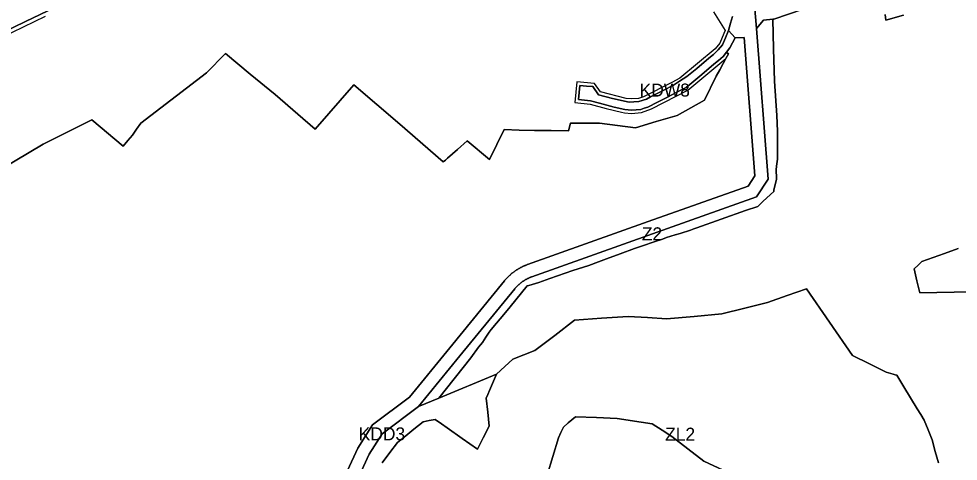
# Model space of a CAD drawing. Extents: x 7439486 to 7443435, y 5551288 to 5554556.
# Drawn here: x 7441363 to 7442085, y 5552904 to 5553244 of the extents above; entities that cross this region are included whole.
import ezdxf

# ---------------------------------------------------------------- set-up
doc = ezdxf.new("R2010")
doc.units = 0
for name, color, linetype in [('linie_rozgraniczajace', 7, 'Continuous'), ('linie_zabudowy_nieprzekraczalne', 7, 'Continuous'), ('oznaczenia_przeznaczen', 7, 'Continuous')]:
    doc.layers.add(name, color=color, linetype=linetype)

msp = doc.modelspace()

# ---------------------------------------------------------------- linework, layer by layer
at = {"layer": 'linie_rozgraniczajace'}
for points in [[(7441331.46, 5553224.04), (7441368.14, 5553241.69), (7441425.2, 5553269.15)], [(7441425.2, 5553269.15), (7441368.14, 5553241.69), (7441331.46, 5553224.04)], [(7441928.74, 5553254.3), (7441930.13, 5553236.35), (7441939.08, 5553120.56), (7441930.19, 5553106.89), (7441850.22, 5553078.58), (7441757.46, 5553045.52), (7441757.43, 5553045.51), (7441757.11, 5553045.39), (7441756.78, 5553045.27), (7441756.46, 5553045.14), (7441756.14, 5553045.01), (7441755.82, 5553044.88), (7441755.5, 5553044.74), (7441755.18, 5553044.6), (7441754.87, 5553044.46), (7441754.56, 5553044.31), (7441754.24, 5553044.16), (7441753.94, 5553044), (7441753.63, 5553043.84), (7441753.32, 5553043.68), (7441753.02, 5553043.52), (7441752.72, 5553043.35), (7441752.42, 5553043.18), (7441752.12, 5553043), (7441751.82, 5553042.82), (7441751.53, 5553042.64), (7441751.23, 5553042.45), (7441750.94, 5553042.26), (7441750.66, 5553042.07), (7441750.37, 5553041.87), (7441750.09, 5553041.67), (7441749.81, 5553041.47), (7441749.53, 5553041.26), (7441749.25, 5553041.05), (7441748.98, 5553040.84), (7441748.71, 5553040.62), (7441748.44, 5553040.4), (7441748.18, 5553040.18), (7441747.91, 5553039.96), (7441747.65, 5553039.73), (7441747.39, 5553039.5), (7441747.14, 5553039.27), (7441746.88, 5553039.03), (7441746.63, 5553038.79), (7441746.39, 5553038.55), (7441746.14, 5553038.3), (7441745.9, 5553038.05), (7441745.66, 5553037.8), (7441745.43, 5553037.55), (7441745.19, 5553037.29), (7441744.96, 5553037.03), (7441744.74, 5553036.77), (7441744.51, 5553036.5), (7441744.29, 5553036.24), (7441702.23, 5552984.74), (7441670.41, 5552945.79), (7441642.42, 5552924.8), (7441632.49, 5552909.09), (7441605.42, 5552850.4)], [(7441736.61, 5552976.52), (7441730.3, 5552970.8), (7441685.94, 5552952.27), (7441710.51, 5552983.35), (7441716.56, 5552991.33), (7441719.61, 5552995.1), (7441722.2, 5552999.2), (7441724.68, 5553002.99), (7441726.14, 5553005.01), (7441737.14, 5553018.12), (7441740.71, 5553022.47), (7441745.2, 5553027.89), (7441753.87, 5553038.56), (7441755.21, 5553038.95), (7441762.78, 5553041.2), (7441771.4, 5553044.24), (7441788.98, 5553050.44), (7441801.31, 5553054.34), (7441808.81, 5553057.13), (7441814.98, 5553059.43), (7441825.4, 5553063.3), (7441836.41, 5553067.18), (7441842.47, 5553069.38), (7441851.6, 5553072.43), (7441857.79, 5553074.51), (7441860.97, 5553075.71), (7441867.54, 5553077.9), (7441871.61, 5553078.77), (7441879.34, 5553081.49), (7441881.93, 5553082.33), (7441884.29, 5553083.17), (7441921.76, 5553096.4), (7441931.26, 5553099.7), (7441935.22, 5553103.66), (7441943.46, 5553111.13), (7441943.49, 5553112.19), (7441945.62, 5553120.7), (7441945.59, 5553121.33), (7441945.2, 5553127.75), (7441945.6, 5553130.5), (7441946.38, 5553135.9), (7441946.44, 5553145.5), (7441946.21, 5553157.51), (7441945.9, 5553169.52), (7441943.93, 5553196.03), (7441943.28, 5553220.79), (7441942.74, 5553243.51), (7441943.58, 5553243.59), (7441965.97, 5553251.17)], [(7441965.97, 5553251.17), (7441943.58, 5553243.59), (7441942.74, 5553243.51), (7441935.65, 5553242.87), (7441930.13, 5553236.35), (7441928.74, 5553254.3)], [(7441670.41, 5552945.79), (7441702.23, 5552984.74), (7441744.29, 5553036.24), (7441744.51, 5553036.5), (7441744.74, 5553036.77), (7441744.96, 5553037.03), (7441745.19, 5553037.29), (7441745.43, 5553037.55), (7441745.66, 5553037.8), (7441745.9, 5553038.05), (7441746.14, 5553038.3), (7441746.39, 5553038.55), (7441746.63, 5553038.79), (7441746.88, 5553039.03), (7441747.14, 5553039.27), (7441747.39, 5553039.5), (7441747.65, 5553039.73), (7441747.91, 5553039.96), (7441748.18, 5553040.18), (7441748.44, 5553040.4), (7441748.71, 5553040.62), (7441748.98, 5553040.84), (7441749.25, 5553041.05), (7441749.53, 5553041.26), (7441749.81, 5553041.47), (7441750.09, 5553041.67), (7441750.37, 5553041.87), (7441750.66, 5553042.07), (7441750.94, 5553042.26), (7441751.23, 5553042.45), (7441751.53, 5553042.64), (7441751.82, 5553042.82), (7441752.12, 5553043), (7441752.42, 5553043.18), (7441752.72, 5553043.35), (7441753.02, 5553043.52), (7441753.32, 5553043.68), (7441753.63, 5553043.84), (7441753.94, 5553044), (7441754.24, 5553044.16), (7441754.56, 5553044.31), (7441754.87, 5553044.46), (7441755.18, 5553044.6), (7441755.5, 5553044.74), (7441755.82, 5553044.88), (7441756.14, 5553045.01), (7441756.46, 5553045.14), (7441756.78, 5553045.27), (7441757.11, 5553045.39), (7441757.43, 5553045.51), (7441757.46, 5553045.52), (7441850.22, 5553078.58), (7441930.19, 5553106.89), (7441939.08, 5553120.56), (7441930.13, 5553236.35), (7441935.65, 5553242.87), (7441942.74, 5553243.51), (7441943.28, 5553220.79), (7441943.93, 5553196.03), (7441945.9, 5553169.52), (7441946.21, 5553157.51), (7441946.44, 5553145.5), (7441946.38, 5553135.9), (7441945.6, 5553130.5), (7441945.2, 5553127.75), (7441945.59, 5553121.33), (7441945.62, 5553120.7), (7441943.49, 5553112.19), (7441943.46, 5553111.13), (7441935.22, 5553103.66), (7441931.26, 5553099.7), (7441921.76, 5553096.4), (7441884.29, 5553083.17), (7441881.93, 5553082.33), (7441879.34, 5553081.49), (7441871.61, 5553078.77), (7441867.54, 5553077.9), (7441860.97, 5553075.71), (7441857.79, 5553074.51), (7441851.6, 5553072.43), (7441842.47, 5553069.38), (7441836.41, 5553067.18), (7441825.4, 5553063.3), (7441814.98, 5553059.43), (7441808.81, 5553057.13), (7441801.31, 5553054.34), (7441788.98, 5553050.44), (7441771.4, 5553044.24), (7441762.78, 5553041.2), (7441755.21, 5553038.95), (7441753.87, 5553038.56), (7441745.2, 5553027.89), (7441740.71, 5553022.47), (7441737.14, 5553018.12), (7441726.14, 5553005.01), (7441724.68, 5553002.99), (7441722.2, 5552999.2), (7441719.61, 5552995.1), (7441716.56, 5552991.33), (7441710.51, 5552983.35)], [(7441751.73, 5553054.01), (7441752.1, 5553054.16), (7441752.47, 5553054.32), (7441752.84, 5553054.47), (7441753.22, 5553054.61), (7441753.59, 5553054.75), (7441753.97, 5553054.89), (7441754.1, 5553054.94), (7441846.88, 5553088), (7441923.66, 5553115.19), (7441928.85, 5553123.17), (7441920.64, 5553229.41), (7441913.66, 5553229.13), (7441908.7, 5553234.81), (7441910.26, 5553240.49), (7441911.64, 5553245.76)], [(7441911.64, 5553245.76), (7441910.26, 5553240.49), (7441908.7, 5553234.81), (7441906.4, 5553229.31), (7441904.09, 5553223.82), (7441900.59, 5553220.11), (7441897.23, 5553216.54), (7441893.59, 5553213.51), (7441884.32, 5553205.78), (7441876.69, 5553199.42), (7441871.03, 5553195.83), (7441866.36, 5553192.86), (7441865.83, 5553192.6), (7441858.95, 5553189.09), (7441848.62, 5553183.81), (7441845.56, 5553181.97), (7441839.6, 5553180.32), (7441835.94, 5553180.11)], [(7442029.06, 5553247.24), (7442029.7, 5553242.69), (7442043.26, 5553246.77)], [(7442043.26, 5553246.77), (7442029.7, 5553242.69), (7442029.06, 5553247.24)], [(7441339.88, 5553122.65), (7441381.86, 5553147.53), (7441419.1, 5553166.1), (7441443.31, 5553145.86), (7441446.85, 5553150.19), (7441450.39, 5553154.53), (7441453.67, 5553159.13), (7441456.95, 5553163.74), (7441507.23, 5553202.43), (7441521.96, 5553217.26), (7441541.02, 5553201.41), (7441560.07, 5553185.57), (7441577.56, 5553170.56), (7441590.88, 5553159.13), (7441620.69, 5553193.1), (7441655.88, 5553162.75), (7441689.41, 5553133.83), (7441691.08, 5553135.29), (7441692.75, 5553136.75), (7441700.3, 5553143.38), (7441707.86, 5553150.01), (7441724.94, 5553135.66), (7441730.53, 5553147.23), (7441736.12, 5553158.8), (7441747.65, 5553158.23), (7441759.5, 5553158.1), (7441771.36, 5553157.96), (7441772.41, 5553157.95), (7441785.74, 5553157.8), (7441787.25, 5553163.56), (7441798.41, 5553163.56), (7441809.58, 5553163.56), (7441823.32, 5553161.83), (7441837.06, 5553160.09), (7441853.07, 5553164.84), (7441869.09, 5553169.59), (7441879.64, 5553175.51), (7441890.2, 5553181.43), (7441899.24, 5553199.74), (7441901.89, 5553204.63), (7441904.53, 5553209.53), (7441906.57, 5553213.29), (7441908.61, 5553217.05), (7441907.69, 5553217.83), (7441907.16, 5553218.28), (7441909.6, 5553221.55), (7441911.63, 5553225.34), (7441913.66, 5553229.13), (7441920.64, 5553229.41), (7441928.85, 5553123.17), (7441923.66, 5553115.19), (7441846.88, 5553088), (7441754.1, 5553054.94), (7441753.97, 5553054.89), (7441753.59, 5553054.75), (7441753.22, 5553054.61), (7441752.84, 5553054.47), (7441752.47, 5553054.32), (7441752.1, 5553054.16), (7441751.73, 5553054.01), (7441751.37, 5553053.85), (7441751, 5553053.69), (7441750.64, 5553053.52), (7441750.28, 5553053.35), (7441749.92, 5553053.17), (7441749.56, 5553053), (7441749.2, 5553052.81), (7441748.85, 5553052.63), (7441748.49, 5553052.44), (7441748.14, 5553052.25), (7441747.79, 5553052.05), (7441747.45, 5553051.85), (7441747.1, 5553051.65), (7441746.76, 5553051.44), (7441746.42, 5553051.24), (7441746.08, 5553051.02), (7441745.74, 5553050.81), (7441745.41, 5553050.59), (7441745.08, 5553050.36), (7441744.75, 5553050.14)], [(7441835.94, 5553180.11), (7441832.27, 5553179.89), (7441819.53, 5553182.48), (7441808.59, 5553185.45), (7441804.33, 5553191.74), (7441799.36, 5553192.21), (7441794.38, 5553192.68), (7441793.35, 5553181.73), (7441797.99, 5553181.29), (7441802.63, 5553180.85), (7441809.6, 5553178.96), (7441815.17, 5553177.45), (7441820.75, 5553175.93), (7441829.05, 5553174.16), (7441834.13, 5553173.66), (7441837.71, 5553173.92), (7441841.29, 5553174.19), (7441843.93, 5553175.11), (7441846.57, 5553176.03), (7441854.12, 5553179.89), (7441861.68, 5553183.74), (7441868.86, 5553187.4), (7441876.03, 5553191.06), (7441878.89, 5553193.45), (7441888.16, 5553201.17), (7441897.43, 5553208.9), (7441901.04, 5553211.91), (7441904.65, 5553214.91), (7441907.16, 5553218.28), (7441907.69, 5553217.83), (7441908.61, 5553217.05), (7441906.57, 5553213.29), (7441904.53, 5553209.53), (7441901.89, 5553204.63), (7441899.24, 5553199.74), (7441890.2, 5553181.43), (7441879.64, 5553175.51), (7441869.09, 5553169.59), (7441853.07, 5553164.84), (7441837.06, 5553160.09), (7441823.32, 5553161.83), (7441809.58, 5553163.56), (7441798.41, 5553163.56), (7441787.25, 5553163.56), (7441785.74, 5553157.8), (7441772.41, 5553157.95), (7441771.36, 5553157.96), (7441759.5, 5553158.1), (7441747.65, 5553158.23), (7441736.12, 5553158.8), (7441730.53, 5553147.23), (7441724.94, 5553135.66), (7441707.86, 5553150.01), (7441700.3, 5553143.38), (7441692.75, 5553136.75), (7441691.08, 5553135.29), (7441689.41, 5553133.83), (7441655.88, 5553162.75), (7441620.69, 5553193.1), (7441590.88, 5553159.13), (7441577.56, 5553170.56), (7441560.07, 5553185.57), (7441541.02, 5553201.41), (7441521.96, 5553217.26), (7441507.23, 5553202.43), (7441456.95, 5553163.74), (7441453.67, 5553159.13), (7441450.39, 5553154.53), (7441446.85, 5553150.19), (7441443.31, 5553145.86), (7441419.1, 5553166.1), (7441381.86, 5553147.53), (7441339.88, 5553122.65)], [(7442085.34, 5553067.35), (7442074.62, 5553063.47), (7442065.99, 5553060.42), (7442057.35, 5553057.38), (7442054.37, 5553054.58), (7442051.38, 5553051.78), (7442053.53, 5553042.45), (7442055.69, 5553033.12), (7442095.27, 5553034.11)], [(7442095.27, 5553034.11), (7442055.69, 5553033.12), (7442053.53, 5553042.45), (7442051.38, 5553051.78), (7442054.37, 5553054.58), (7442057.35, 5553057.38), (7442065.99, 5553060.42), (7442074.62, 5553063.47), (7442085.34, 5553067.35)], [(7441596.56, 5552855.07), (7441623.69, 5552913.88), (7441634.95, 5552931.7), (7441663.44, 5552953.06), (7441694.48, 5552991.06), (7441736.55, 5553042.56), (7441736.8, 5553042.87), (7441737.06, 5553043.18), (7441737.32, 5553043.48), (7441737.59, 5553043.78), (7441737.85, 5553044.08), (7441738.12, 5553044.38), (7441738.4, 5553044.67), (7441738.67, 5553044.96), (7441738.95, 5553045.24), (7441739.23, 5553045.53), (7441739.51, 5553045.81), (7441739.8, 5553046.09), (7441740.09, 5553046.37), (7441740.38, 5553046.64), (7441740.68, 5553046.91), (7441740.98, 5553047.18), (7441741.28, 5553047.44), (7441741.58, 5553047.7), (7441741.89, 5553047.96), (7441742.19, 5553048.21), (7441742.5, 5553048.47), (7441742.82, 5553048.71), (7441743.13, 5553048.96), (7441743.45, 5553049.2), (7441743.77, 5553049.44), (7441744.1, 5553049.68), (7441744.42, 5553049.91), (7441744.75, 5553050.14), (7441745.08, 5553050.36), (7441745.41, 5553050.59), (7441745.74, 5553050.81), (7441746.08, 5553051.02), (7441746.42, 5553051.24), (7441746.76, 5553051.44), (7441747.1, 5553051.65), (7441747.45, 5553051.85), (7441747.79, 5553052.05), (7441748.14, 5553052.25), (7441748.49, 5553052.44), (7441748.85, 5553052.63), (7441749.2, 5553052.81), (7441749.56, 5553053), (7441749.92, 5553053.17), (7441750.28, 5553053.35), (7441750.64, 5553053.52), (7441751, 5553053.69), (7441751.37, 5553053.85), (7441751.73, 5553054.01)], [(7441744.75, 5553050.14), (7441744.42, 5553049.91), (7441744.1, 5553049.68), (7441743.77, 5553049.44), (7441743.45, 5553049.2), (7441743.13, 5553048.96), (7441742.82, 5553048.71), (7441742.5, 5553048.47), (7441742.19, 5553048.21), (7441741.89, 5553047.96), (7441741.58, 5553047.7), (7441741.28, 5553047.44), (7441740.98, 5553047.18), (7441740.68, 5553046.91), (7441740.38, 5553046.64), (7441740.09, 5553046.37), (7441739.8, 5553046.09), (7441739.51, 5553045.81), (7441739.23, 5553045.53), (7441738.95, 5553045.24), (7441738.67, 5553044.96), (7441738.4, 5553044.67), (7441738.12, 5553044.38), (7441737.85, 5553044.08), (7441737.59, 5553043.78), (7441737.32, 5553043.48), (7441737.06, 5553043.18), (7441736.8, 5553042.87), (7441736.55, 5553042.56), (7441694.48, 5552991.06), (7441663.44, 5552953.06), (7441634.95, 5552931.7), (7441623.69, 5552913.88), (7441596.56, 5552855.07)], [(7441642.52, 5552902.6), (7441648.31, 5552910.37), (7441654.1, 5552918.15), (7441660.48, 5552923.26), (7441666.86, 5552928.37), (7441670.36, 5552931.17), (7441673.86, 5552933.97), (7441678.46, 5552934.97), (7441683.07, 5552935.96), (7441688.03, 5552932.47), (7441692.37, 5552929.41), (7441703.97, 5552921.23), (7441715.57, 5552913.05), (7441720.17, 5552921.86), (7441724.77, 5552930.67), (7441723.6, 5552941.48), (7441722.43, 5552952.24), (7441723.67, 5552955.14), (7441724.9, 5552958.05), (7441730.3, 5552970.8), (7441736.61, 5552976.52), (7441742.91, 5552982.24), (7441751.36, 5552985.5), (7441759.82, 5552988.77), (7441775.07, 5553000.49), (7441790.32, 5553012.2), (7441810.9, 5553013.62), (7441831.48, 5553015.04), (7441846.27, 5553014.17), (7441861.06, 5553013.29), (7441882.35, 5553015.14), (7441903.64, 5553016.99), (7441921.2, 5553021.4), (7441938.76, 5553025.81), (7441953.75, 5553031.07), (7441968.73, 5553036.32), (7441986.37, 5553010.69), (7442004.01, 5552985.06), (7442016.92, 5552978.61), (7442029.84, 5552972.16), (7442035.24, 5552970.65), (7442036.7, 5552970.24), (7442038.15, 5552969.83), (7442043.42, 5552961.01), (7442053.81, 5552944.07), (7442056.47, 5552939.77), (7442059.13, 5552935.46), (7442062.18, 5552927.78), (7442065.24, 5552920.09), (7442067.62, 5552911.29), (7442069.99, 5552902.5)], [(7442069.99, 5552902.5), (7442067.62, 5552911.29), (7442065.24, 5552920.09), (7442062.18, 5552927.78), (7442059.13, 5552935.46), (7442056.47, 5552939.77), (7442053.81, 5552944.07), (7442043.42, 5552961.01), (7442038.15, 5552969.83), (7442036.7, 5552970.24), (7442035.24, 5552970.65), (7442029.84, 5552972.16), (7442016.92, 5552978.61), (7442004.01, 5552985.06), (7441986.37, 5553010.69), (7441968.73, 5553036.32), (7441953.75, 5553031.07), (7441938.76, 5553025.81), (7441921.2, 5553021.4), (7441903.64, 5553016.99), (7441882.35, 5553015.14), (7441861.06, 5553013.29), (7441846.27, 5553014.17), (7441831.48, 5553015.04), (7441810.9, 5553013.62), (7441790.32, 5553012.2), (7441775.07, 5553000.49), (7441759.82, 5552988.77), (7441751.36, 5552985.5), (7441742.91, 5552982.24), (7441736.61, 5552976.52)], [(7441710.51, 5552983.35), (7441685.94, 5552952.27), (7441670.41, 5552945.79)], [(7441605.42, 5552850.4), (7441632.49, 5552909.09), (7441642.42, 5552924.8), (7441670.41, 5552945.79), (7441685.94, 5552952.27), (7441730.3, 5552970.8), (7441724.9, 5552958.05), (7441723.67, 5552955.14), (7441722.43, 5552952.24), (7441723.6, 5552941.48), (7441724.77, 5552930.67), (7441720.17, 5552921.86), (7441715.57, 5552913.05), (7441703.97, 5552921.23), (7441692.37, 5552929.41), (7441688.03, 5552932.47), (7441683.07, 5552935.96), (7441678.46, 5552934.97), (7441673.86, 5552933.97), (7441670.36, 5552931.17), (7441666.86, 5552928.37), (7441660.48, 5552923.26), (7441654.1, 5552918.15), (7441648.31, 5552910.37), (7441642.52, 5552902.6)], [(7441769.33, 5552893.1), (7441773.68, 5552907.37), (7441778.02, 5552921.63), (7441779.85, 5552925.84), (7441781.68, 5552930.05), (7441785.45, 5552933.18), (7441788.28, 5552935.54), (7441791.11, 5552937.89), (7441807.13, 5552937.31), (7441823.15, 5552936.73), (7441824.73, 5552936.47), (7441833.15, 5552935.12), (7441841.57, 5552933.76), (7441850, 5552932.4), (7441857.58, 5552927.58), (7441865.15, 5552922.75), (7441877.41, 5552913.34), (7441889.66, 5552903.94), (7441904.49, 5552896.93)], [(7441904.49, 5552896.93), (7441889.66, 5552903.94), (7441877.41, 5552913.34), (7441865.15, 5552922.75), (7441857.58, 5552927.58), (7441850, 5552932.4), (7441841.57, 5552933.76), (7441833.15, 5552935.12), (7441824.73, 5552936.47), (7441823.15, 5552936.73), (7441807.13, 5552937.31), (7441791.11, 5552937.89), (7441788.28, 5552935.54), (7441785.45, 5552933.18), (7441781.68, 5552930.05), (7441779.85, 5552925.84), (7441778.02, 5552921.63), (7441773.68, 5552907.37), (7441769.33, 5552893.1)]]:
    msp.add_lwpolyline(points, dxfattribs=at)
msp.add_lwpolyline([(7441793.35, 5553181.73), (7441794.38, 5553192.68), (7441799.36, 5553192.21), (7441804.33, 5553191.74), (7441808.59, 5553185.45), (7441819.53, 5553182.48), (7441832.27, 5553179.89), (7441835.94, 5553180.11), (7441839.6, 5553180.32), (7441845.56, 5553181.97), (7441848.62, 5553183.81), (7441858.95, 5553189.09), (7441865.83, 5553192.6), (7441866.36, 5553192.86), (7441871.03, 5553195.83), (7441876.69, 5553199.42), (7441884.32, 5553205.78), (7441893.59, 5553213.51), (7441897.23, 5553216.54), (7441900.59, 5553220.11), (7441904.09, 5553223.82), (7441906.4, 5553229.31), (7441908.7, 5553234.81), (7441913.66, 5553229.13), (7441911.63, 5553225.34), (7441909.6, 5553221.55), (7441907.16, 5553218.28), (7441904.65, 5553214.91), (7441901.04, 5553211.91), (7441897.43, 5553208.9), (7441888.16, 5553201.17), (7441878.89, 5553193.45), (7441876.03, 5553191.06), (7441868.86, 5553187.4), (7441861.68, 5553183.74), (7441854.12, 5553179.89), (7441846.57, 5553176.03), (7441843.93, 5553175.11), (7441841.29, 5553174.19), (7441837.71, 5553173.92), (7441834.13, 5553173.66), (7441829.05, 5553174.16), (7441820.75, 5553175.93), (7441815.17, 5553177.45), (7441809.6, 5553178.96), (7441802.63, 5553180.85), (7441797.99, 5553181.29)], close=True, dxfattribs=at)
at = {"layer": 'linie_zabudowy_nieprzekraczalne'}
for points in [[(7441332.65, 5553221.29), (7441383.71, 5553245.85)], [(7441897.21, 5553249.13), (7441906.07, 5553234.99), (7441905.08, 5553232.64), (7441901.96, 5553225.21), (7441898.43, 5553220.8), (7441871.32, 5553198.2)], [(7441871.32, 5553198.2), (7441864.99, 5553194.98), (7441843.21, 5553183.86), (7441839.55, 5553182.58), (7441833.89, 5553182.22), (7441829.91, 5553182.61), (7441810.14, 5553187.62), (7441805.74, 5553194.11), (7441792.13, 5553195.4), (7441790.62, 5553179.47), (7441802.39, 5553178.36), (7441814.52, 5553175.03), (7441826.5, 5553172.15), (7441828.66, 5553171.68), (7441834.1, 5553171.15), (7441841.81, 5553171.72), (7441849.56, 5553174.76), (7441859.04, 5553179.59), (7441877.42, 5553188.96), (7441894.4, 5553203.12), (7441906.57, 5553213.29)]]:
    msp.add_lwpolyline(points, dxfattribs=at)

# ---------------------------------------------------------------- texts
at = {"layer": 'oznaczenia_przeznaczen'}
for s, p in [('KDW8', (7441840.33, 5553184.09)), ('Z2', (7441842.03, 5553073.58)), ('KDD3', (7441624.39, 5552919.8)), ('ZL2', (7441859.93, 5552919.57))]:
    msp.add_text(s, height=10, dxfattribs=at).set_placement(p)

doc.saveas('drawing.dxf')
